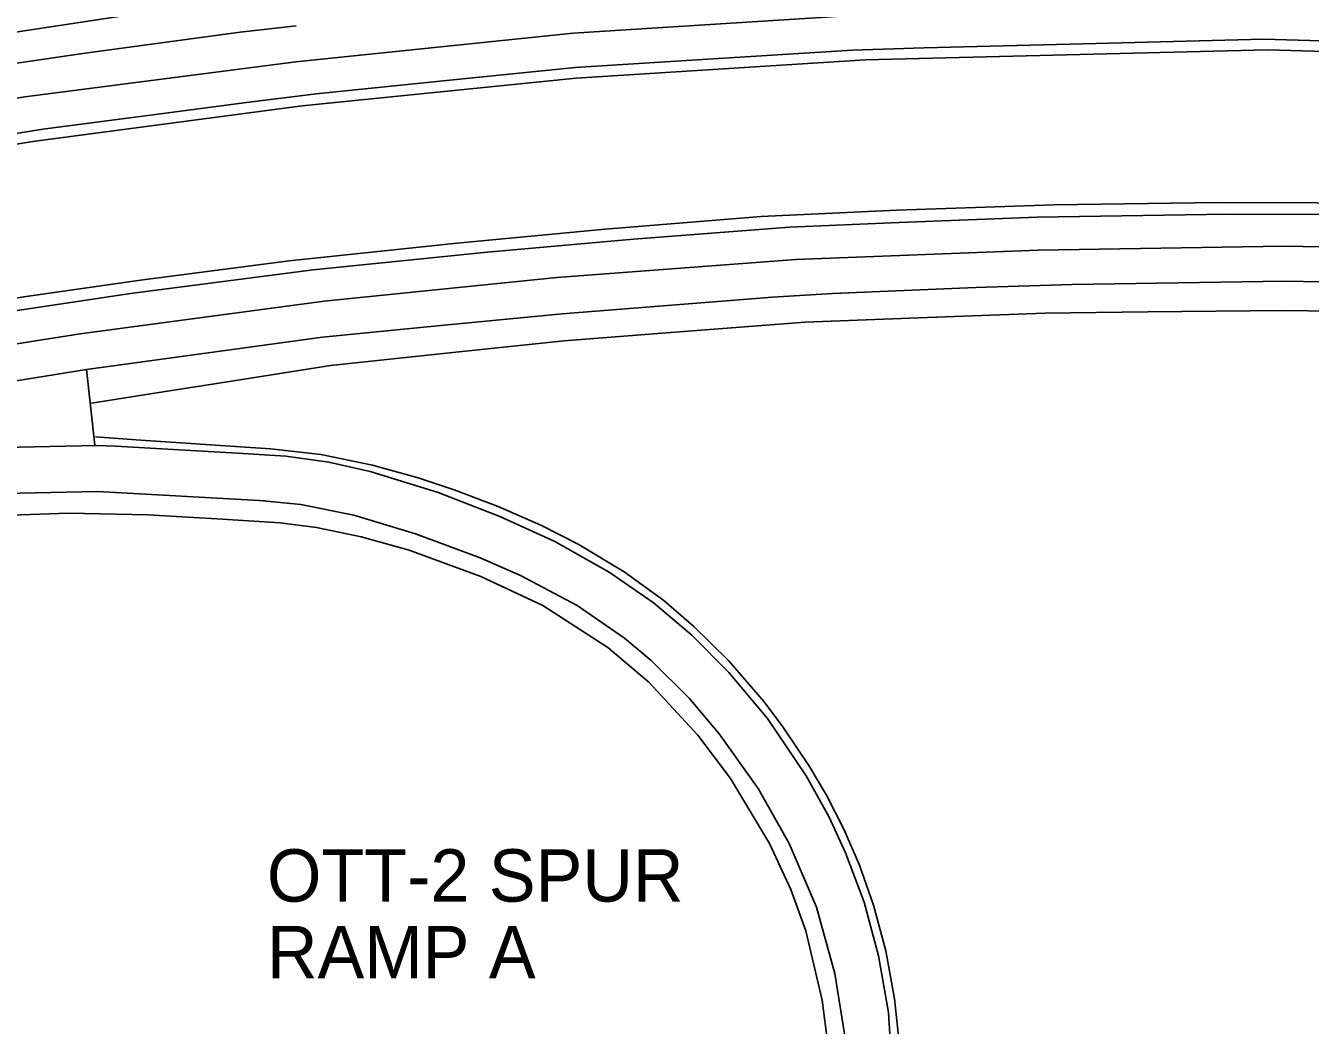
# Model space of a CAD drawing. Extents: x 1855721 to 1876784, y 662259 to 674089.
# Drawn here: x 1857975.7 to 1858417, y 672370.5 to 672713.9 of the extents above; entities that cross this region are included whole.
import ezdxf

# ---------------------------------------------------------------- set-up
doc = ezdxf.new("R2010")
doc.units = 0
for name, color, linetype in [('_CIVIL_CONSTRUCTION', 7, 'Continuous'), ('GE_X_Alignment_100_Bearings', 7, 'Continuous'), ('GE_X_Alignment_100_Cardinal_Points', 7, 'Continuous'), ('GE_X_Alignment_100_Curve_Data', 7, 'Continuous'), ('SC_Scratch1', 7, 'Continuous')]:
    doc.layers.add(name, color=color, linetype=linetype)

msp = doc.modelspace()

# ---------------------------------------------------------------- linework, layer by layer
at = {"layer": '_CIVIL_CONSTRUCTION'}
for points in [[(1857007, 672377.05), (1857077.72, 672414.14), (1857118.52, 672434.8), (1857166.11, 672457.32), (1857210.93, 672477.94), (1857256.53, 672497.89), (1857275.95, 672506.24), (1857341.89, 672532.95), (1857381.62, 672548.33), (1857413.65, 672559.81), (1857461.27, 672576.85), (1857504.51, 672591.27), (1857540.84, 672602.91), (1857584, 672616.08), (1857622.18, 672626.6), (1857678.12, 672641.66), (1857727.56, 672653.91), (1857874.33, 672684.7), (1857922.22, 672692.91), (1857962.37, 672699.64), (1857996.16, 672704.55), (1858049.43, 672711.68), (1858068.6, 672713.95)], [(1857999.53, 672569.87), (1857996.61, 672595.79), (1858077.64, 672606.93), (1858118.31, 672610.94), (1858159.97, 672614.97), (1858232.24, 672620.65), (1858252.87, 672621.9), (1858302.14, 672623.96), (1858335.21, 672625.08), (1858407.95, 672626.18), (1858488.25, 672624.81), (1858569.03, 672620.88), (1858650.77, 672615.02), (1858706.13, 672609.52), (1858734.28, 672606.71), (1858823.5, 672594.64), (1858902.94, 672581.37), (1858944.96, 672573.37), (1858984.12, 672565.92), (1859022.95, 672557.68), (1859105.37, 672539.8)], [(1856754.92, 672091.19), (1856827.02, 672140.87), (1856894.25, 672184.63), (1856969.22, 672231.5), (1857038.15, 672271.06), (1857107.02, 672308.1), (1857177.12, 672343.39), (1857213.45, 672360.39), (1857228.68, 672366.04), (1857290.15, 672384.29), (1857320.98, 672395.34), (1857391.27, 672423.57), (1857462.56, 672450.07), (1857553.44, 672480.94), (1857590.09, 672492.02), (1857670.4, 672512.63), (1857717.45, 672522.39), (1857812.47, 672538.24), (1857861.98, 672544.31), (1857912.93, 672549.5), (1857962.94, 672553.14), (1858000.39, 672553.88), (1858058.01, 672550.66)], [(1858057.45, 672550.69), (1858070.19, 672549.45), (1858088.47, 672545.81), (1858109.64, 672539.41), (1858131.84, 672531.08), (1858145.67, 672525.06), (1858165.14, 672514.75), (1858181.46, 672503.52), (1858190.57, 672495.85), (1858203.57, 672482.92), (1858213.93, 672470.69), (1858227.29, 672451.83), (1858237.98, 672433.02), (1858247.31, 672411.1), (1858253.68, 672388.29), (1858256.92, 672367.62)]]:
    msp.add_lwpolyline(points, dxfattribs=at)
at = {"layer": 'GE_X_Alignment_100_Bearings'}
for points in [[(1857530.71, 672587), (1857588.26, 672604.8), (1857614.97, 672612.46), (1857680.21, 672629.64), (1857730.24, 672642.05), (1857881.01, 672674.13), (1857975.46, 672689.54), (1858068.51, 672701.58), (1858163.83, 672711.37), (1858263.32, 672717.66), (1858402.31, 672721.48), (1858580.77, 672715.58), (1858680.94, 672707.57), (1858786.38, 672695.42), (1858835.49, 672688.75), (1858884.15, 672681), (1858917.61, 672674.84), (1859035.65, 672651.94), (1859037.18, 672651.78), (1859180.87, 672620.07)], [(1857520.47, 672496.11), (1857557.87, 672508.34), (1857658.83, 672538.03), (1857741.72, 672559.31), (1857825.42, 672578.08), (1857911.7, 672594.99), (1857994.46, 672608.07), (1858078.29, 672619.25), (1858158.12, 672627.41), (1858240.31, 672633.64), (1858323.44, 672636.86), (1858407.79, 672638.18), (1858487.86, 672636.86), (1858570.33, 672632.98), (1858652.9, 672626.79), (1858734.38, 672618.74), (1858824.74, 672606.62), (1858905, 672593.29), (1858987.11, 672577.5), (1859080.51, 672557.59), (1859107.52, 672551.69)]]:
    msp.add_lwpolyline(points, dxfattribs=at)
at = {"layer": 'GE_X_Alignment_100_Cardinal_Points'}
msp.add_lwpolyline([(1857996.61, 672595.79), (1857914.23, 672582.6), (1857828.33, 672566.05), (1857745.04, 672547.1), (1857664.56, 672526.89), (1857714.36, 672537.66), (1857738.83, 672542.62), (1857762.91, 672546.51), (1857810.66, 672553.89), (1857861.27, 672559.83), (1857911.72, 672565.01), (1857962.67, 672568.97), (1858000.08, 672569.74)], dxfattribs=at)
at = {"layer": 'GE_X_Alignment_100_Curve_Data'}
for points in [[(1858456.39, 672707.69), (1858400.9, 672709.27), (1858343.37, 672707.81), (1858284.38, 672706.32), (1858259.7, 672705.54), (1858208.2, 672702.33), (1858164.51, 672699.61), (1858120.3, 672695.09), (1858075.51, 672690.5), (1858051.54, 672687.52), (1858017.66, 672683.1), (1857981.56, 672678.38), (1857937.12, 672671.14), (1857895.65, 672664.24), (1857852.15, 672655.75), (1857818.12, 672648.63), (1857789.27, 672642.6), (1857741.22, 672632.55), (1857693.19, 672621.06), (1857645.48, 672608.58), (1857609.29, 672598.81), (1857576.29, 672589.02), (1857536.78, 672576.97), (1857505.48, 672567.06)], [(1858436.97, 672649.1), (1858388.49, 672649.24), (1858323.2, 672648.18), (1858275.73, 672646.29), (1858238.08, 672644.74), (1858184.47, 672640.6), (1858134.23, 672636.18), (1858074.43, 672630.09), (1858011.67, 672621.95), (1857958.28, 672613.94), (1857907.4, 672605.7), (1857860.17, 672596.51), (1857808.51, 672586.06), (1857739.21, 672570.69), (1857679.68, 672555.34), (1857638.32, 672544), (1857567.86, 672523.13), (1857517.17, 672507.16)], [(1858273.8, 672347.23), (1858272.03, 672374.91), (1858268.67, 672394.39), (1858263.7, 672412.78), (1858257.34, 672429.8), (1858251.67, 672442.03), (1858243.85, 672456.2), (1858230.52, 672475.88), (1858217.29, 672491.78), (1858204.5, 672504.6), (1858191.26, 672515.76), (1858176.19, 672526.24), (1858157.51, 672536.7), (1858138.56, 672545.37), (1858117.46, 672553.52), (1858094.07, 672560.82), (1858079.88, 672564), (1858065.12, 672566.07), (1858050.37, 672567), (1858006.53, 672569.49), (1858000.08, 672569.74)]]:
    msp.add_lwpolyline(points, dxfattribs=at)
at = {"layer": 'SC_Scratch1'}
for points in [[(1857516.32, 672608.2), (1857586.79, 672629.4), (1857589.02, 672628.97), (1857610.4, 672634.21), (1857675.16, 672651.48), (1857726.64, 672663.94), (1857811.29, 672681.88), (1857885.87, 672697.34), (1857960.75, 672710.03), (1858021.32, 672719.22), (1858068.42, 672726.15)], [(1857506.57, 672562.92), (1857534.77, 672571.96), (1857551.31, 672577.06), (1857597.87, 672591.2), (1857617.62, 672596.89), (1857630.9, 672600.47), (1857662.66, 672608.93), (1857685.26, 672614.94), (1857734.36, 672627.08), (1857882.24, 672658.37), (1857959.06, 672671.07), (1857978.13, 672674.21), (1858070.72, 672686.42), (1858164.82, 672695.89), (1858264.2, 672702.26), (1858402.25, 672705.67), (1858518.07, 672702.3)], [(1857501.49, 672506.22), (1857537.42, 672518.04), (1857589.99, 672533.97), (1857642.35, 672549.51), (1857696.62, 672563.83), (1857744.81, 672575.9), (1857805.6, 672589.43), (1857869.58, 672602.42), (1857922.28, 672612.25), (1857975.06, 672620.74), (1858015.17, 672626.5), (1858066.18, 672633.11), (1858123.96, 672639.29), (1858174.71, 672644.1), (1858228.33, 672648.41), (1858274.92, 672650.54), (1858329.03, 672652.42), (1858385.33, 672653.22), (1858452.95, 672652.96)], [(1858441.57, 672615.61), (1858407.97, 672616.13), (1858361.11, 672615.61), (1858325.75, 672615.2), (1858282.4, 672613.55), (1858243.49, 672612.06), (1858194.39, 672608.28), (1858160.69, 672605.67), (1858123.42, 672601.74), (1858080.42, 672597.21), (1858045.73, 672591.76), (1858022.95, 672588.18), (1857998.33, 672584.32)], [(1857999.68, 672572.67), (1858015.32, 672571.61), (1858054.62, 672568.95), (1858059.81, 672568.6), (1858077.15, 672566.61), (1858094.9, 672562.98), (1858110.48, 672558.62), (1858122.91, 672554.46), (1858138, 672548.73), (1858152.62, 672542.34), (1858165.52, 672535.81), (1858181.28, 672526.35), (1858194.86, 672516.46), (1858205.26, 672507.58), (1858217.12, 672495.87), (1858229.34, 672481.68), (1858235.84, 672473.1), (1858244.76, 672459.79), (1858250.74, 672449.58), (1858256.7, 672437.93), (1858262.1, 672425.49), (1858266.93, 672411.84), (1858271.15, 672396.07), (1858274.17, 672379.65), (1858275.9, 672363.54)], [(1857964.1, 672545.6), (1857990.41, 672546.51), (1858017.73, 672545.9), (1858041.36, 672544.55), (1858063.1, 672543.2), (1858075.64, 672541.57), (1858091.01, 672538.39), (1858107.42, 672533.72), (1858132.04, 672524.74), (1858153.33, 672514.72), (1858175.71, 672500.38), (1858189.79, 672488.38), (1858206.58, 672470.23), (1858217.77, 672455.28), (1858231.2, 672432.98), (1858238.54, 672417.17), (1858243.64, 672403.01), (1858249.35, 672379.13), (1858251.28, 672364.07)]]:
    msp.add_lwpolyline(points, dxfattribs=at)

# ---------------------------------------------------------------- texts
for s, p in [('OTT-2 SPUR', (1858058.59, 672413.01)), ('RAMP A', (1858058.59, 672386.68))]:
    msp.add_text(s, height=18, dxfattribs=at).set_placement(p)

doc.saveas('drawing.dxf')
